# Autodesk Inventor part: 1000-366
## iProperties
Created: 2007-03
Part Number: 1000-366
Document SubType Name: Modeling
Designer: Andy Moles
Material: Steel
Mass: 101.663 g
Surface Area: 87.3571 cm^2
Volume: 12.9506 cm^3
Density: 7.85 g/cm^3
Author: Andy Moles
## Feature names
1. Base1
